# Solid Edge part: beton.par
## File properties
Author: user
Template: iso part.par
Last saved by: user
Revision: 1
Application: Solid Edge
Accuracy: 0.990
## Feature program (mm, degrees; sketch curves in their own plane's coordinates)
sketch for "unnamed Protrusion 1" plane through (0, 0, 0) normal (0, -1, 0) x-axis (1, 0, 0)
  line (-500, 500) -> (-500, -500)
  line (-500, -500) -> (500, -500)
  line (500, -500) -> (500, 500)
  line (500, 500) -> (-500, 500)
extrude "unnamed Protrusion 1" add finite 100 along -normal
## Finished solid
Body 1: solid body, 6 faces, 12 edges, 8 vertices.
  Faces by surface: plane 6
  Edges by curve: line 12
Bounding box of the edges (mm): 1000.000 x 100.000 x 1000.000, from (-500, 0, -500) to (500, 100, 500).
Planar faces by outward normal: +x 1, +y 1, +z 1, -x 1, -y 1, -z 1
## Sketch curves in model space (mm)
line (500, 0, -500) -> (500, 0, 500)
line (500, 0, 500) -> (-500, 0, 500)
line (-500, 0, 500) -> (-500, 0, -500)
line (-500, 0, -500) -> (500, 0, -500)
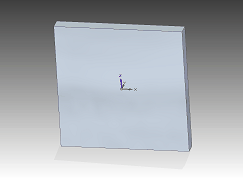
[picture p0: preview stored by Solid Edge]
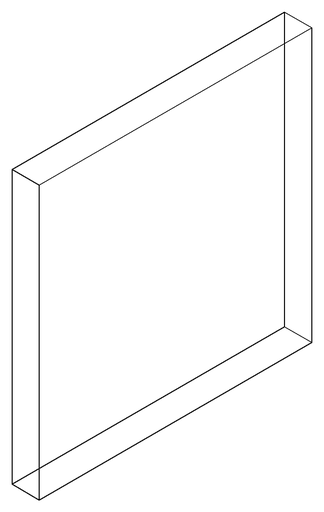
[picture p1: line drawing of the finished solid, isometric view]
